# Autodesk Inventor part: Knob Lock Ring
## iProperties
Shininess: 64.0
Length Units: 11272
Angle Units: 11279
Time Units: 11290
Mass Units: 11286
Length Display Precision: 3
Angle Display Precision: 2
Compacted: True
Part Number: Knob Lock Ring
Document SubType Name: Modeling
Created: 2003-08
Designer: FT User
Manufacturer: Standard
Standards Organization: Custom
Density: 0.0
Volumn: 0.0
Area: 0.0
PropertySet Name: Model Information
Control State: 0
Master: False
Checked Out: False
Author: FT User
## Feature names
1. Extrusion1
2. Extrusion2
